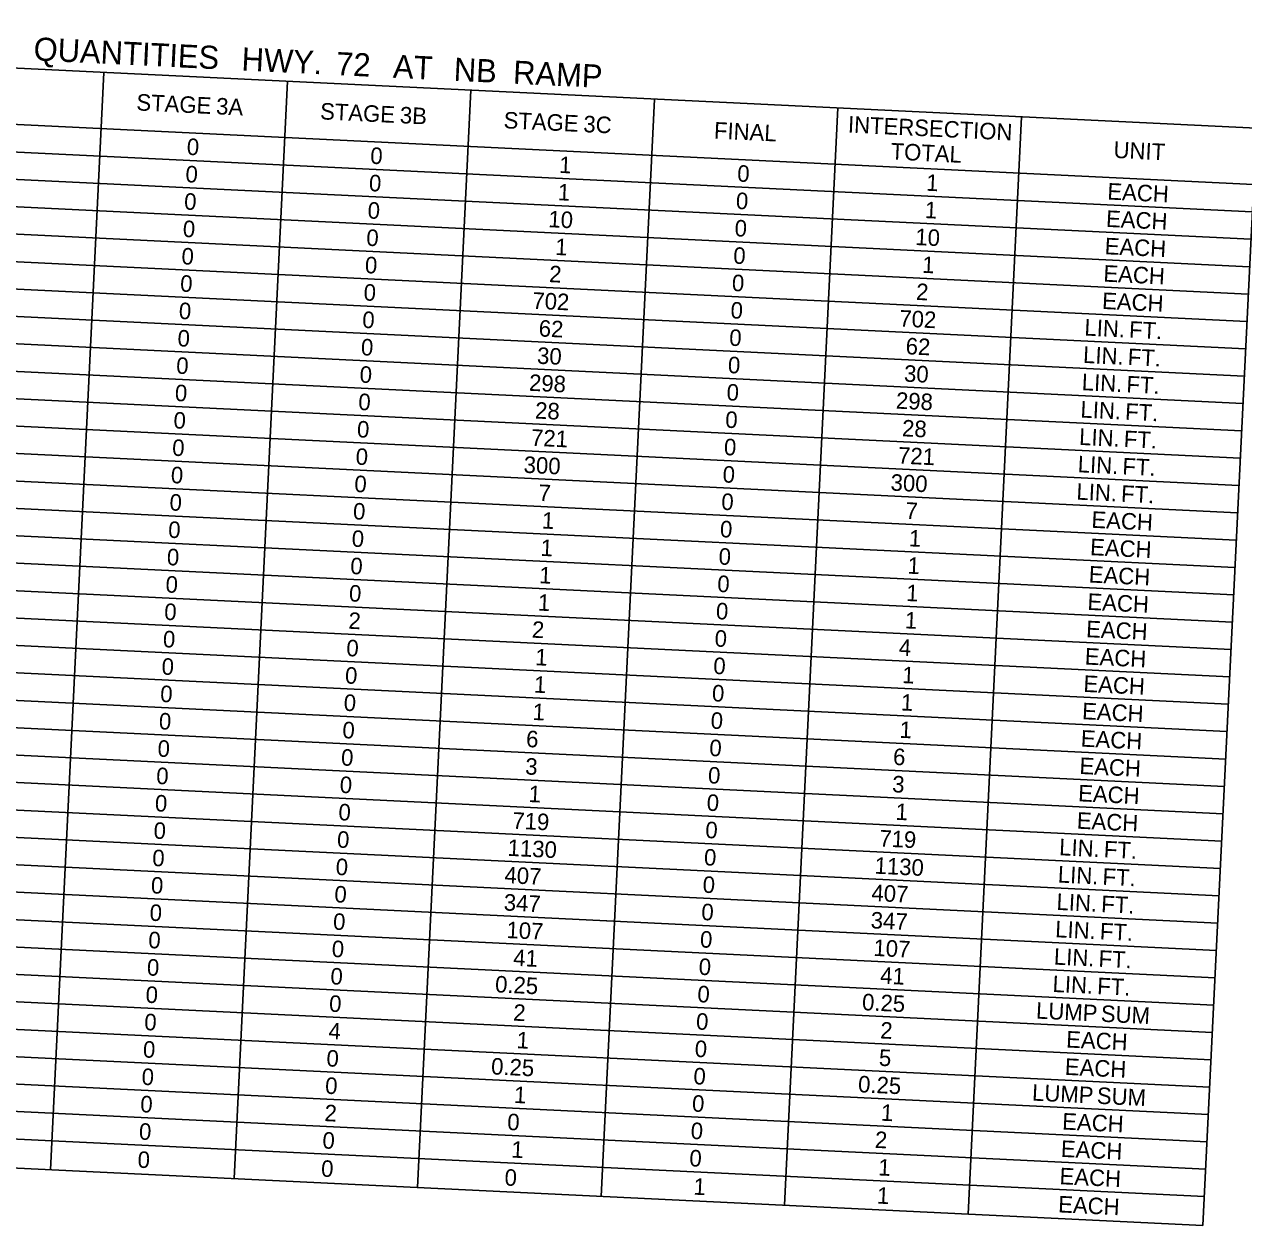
# Model space of a CAD drawing. Extents: x 668933 to 670801, y 741155 to 743955.
# Drawn here: x 669245.8 to 669430.3, y 743471 to 743652.7 of the extents above; entities that cross this region are included whole.
import ezdxf

# ---------------------------------------------------------------- set-up
doc = ezdxf.new("R2010")
doc.units = 0
doc.layers.add('R_Dimension', color=7, linetype='Continuous')

msp = doc.modelspace()

# ---------------------------------------------------------------- linework, layer by layer
at = {"layer": 'R_Dimension'}
for p, q in [((669108.37, 743652.72), (669432.18, 743637)), ((669249.79, 743479.42), (669257.86, 743645.46)), ((669107.96, 743644.2), (669431.76, 743628.48)), ((669277.55, 743478.07), (669285.61, 743644.12)), ((669305.3, 743476.73), (669313.37, 743642.77)), ((669333.06, 743475.38), (669341.12, 743641.42)), ((669107.76, 743640.06), (669431.56, 743624.34)), ((669360.81, 743474.03), (669368.88, 743640.07)), ((669388.57, 743472.68), (669396.63, 743638.72)), ((669107.56, 743635.92), (669431.36, 743620.2)), ((669424.11, 743470.96), (669432.18, 743637)), ((669107.35, 743631.78), (669431.16, 743616.06)), ((669107.15, 743627.65), (669430.96, 743611.92)), ((669106.95, 743623.51), (669430.76, 743607.78)), ((669106.75, 743619.37), (669430.56, 743603.64)), ((669106.55, 743615.23), (669430.36, 743599.51)), ((669106.35, 743611.09), (669430.16, 743595.37)), ((669106.15, 743606.95), (669429.95, 743591.23)), ((669105.95, 743602.81), (669429.75, 743587.09)), ((669105.75, 743598.67), (669429.55, 743582.95)), ((669105.55, 743594.54), (669429.35, 743578.81)), ((669105.34, 743590.4), (669429.15, 743574.67)), ((669105.14, 743586.26), (669428.95, 743570.53)), ((669104.94, 743582.12), (669428.75, 743566.39)), ((669104.74, 743577.98), (669428.55, 743562.26)), ((669104.54, 743573.84), (669428.35, 743558.12)), ((669104.34, 743569.7), (669428.15, 743553.98)), ((669104.14, 743565.56), (669427.94, 743549.84)), ((669103.94, 743561.42), (669427.74, 743545.7)), ((669103.74, 743557.29), (669427.54, 743541.56)), ((669103.54, 743553.15), (669427.34, 743537.42)), ((669103.33, 743549.01), (669427.14, 743533.28)), ((669103.13, 743544.87), (669426.94, 743529.14)), ((669102.93, 743540.73), (669426.74, 743525.01)), ((669102.73, 743536.59), (669426.54, 743520.87)), ((669102.53, 743532.45), (669426.34, 743516.73)), ((669102.33, 743528.31), (669426.14, 743512.59)), ((669102.13, 743524.17), (669425.93, 743508.45)), ((669101.93, 743520.04), (669425.73, 743504.31)), ((669101.73, 743515.9), (669425.53, 743500.17)), ((669101.53, 743511.76), (669425.33, 743496.03)), ((669101.32, 743507.62), (669425.13, 743491.89)), ((669101.12, 743503.48), (669424.93, 743487.76)), ((669100.92, 743499.34), (669424.73, 743483.62)), ((669100.72, 743495.2), (669424.53, 743479.48)), ((669100.52, 743491.06), (669424.33, 743475.34)), ((669100.31, 743486.68), (669424.11, 743470.96))]:
    msp.add_line(p, q, dxfattribs=at)

# ---------------------------------------------------------------- texts
for s, height, p in [(' QUANTITIES', 3.5, (669245.85, 743647.35)), (' HWY.', 3.5, (669277.31, 743645.82)), (' 72', 3.5, (669291.6, 743645.12)), (' AT', 3.5, (669300.22, 743644.71)), (' NB', 3.5, (669309.41, 743644.26)), (' RAMP', 3.5, (669318.38, 743643.82)), ('STAGE', 2.5, (669262.72, 743639.71)), (' 3A', 2.5, (669273.85, 743639.17)), ('STAGE', 2.5, (669290.51, 743638.36)), (' 3B', 2.5, (669301.64, 743637.82)), ('STAGE', 2.5, (669318.27, 743637.01)), (' 3C', 2.5, (669329.4, 743636.47)), ('FINAL', 2.5, (669350.09, 743635.46)), ('INTERSECTION', 2.5, (669370.36, 743636.36)), ('0', 2.5, (669270.34, 743632.99)), ('0', 2.5, (669298.1, 743631.64)), ('TOTAL', 2.5, (669376.81, 743632.29)), ('UNIT', 2.5, (669410.53, 743632.53)), ('1', 2.5, (669326.67, 743630.26)), ('0', 2.5, (669270.14, 743628.85)), ('0', 2.5, (669297.9, 743627.5)), ('0', 2.5, (669353.61, 743628.95)), ('1', 2.5, (669382.18, 743627.56)), ('1', 2.5, (669326.47, 743626.12)), ('EACH', 2.5, (669409.6, 743626.23)), ('0', 2.5, (669269.94, 743624.71)), ('0', 2.5, (669353.41, 743624.81)), ('0', 2.5, (669297.7, 743623.36)), ('10', 2.5, (669325.04, 743622.04)), ('1', 2.5, (669381.98, 743623.42)), ('EACH', 2.5, (669409.4, 743622.09)), ('0', 2.5, (669269.74, 743620.57)), ('0', 2.5, (669353.21, 743620.67)), ('0', 2.5, (669297.5, 743619.23)), ('10', 2.5, (669380.55, 743619.34)), ('0', 2.5, (669269.54, 743616.43)), ('1', 2.5, (669326.07, 743617.84)), ('0', 2.5, (669353.01, 743616.53)), ('EACH', 2.5, (669409.2, 743617.95)), ('0', 2.5, (669297.29, 743615.09)), ('1', 2.5, (669381.58, 743615.14)), ('2', 2.5, (669325.16, 743613.73)), ('EACH', 2.5, (669409, 743613.81)), ('0', 2.5, (669269.34, 743612.3)), ('0', 2.5, (669297.09, 743610.95)), ('0', 2.5, (669352.8, 743612.39)), ('2', 2.5, (669380.67, 743611.04)), ('702', 2.5, (669322.62, 743609.71)), ('EACH', 2.5, (669408.8, 743609.67)), ('0', 2.5, (669269.14, 743608.16)), ('0', 2.5, (669352.6, 743608.25)), ('0', 2.5, (669296.89, 743606.81)), ('62', 2.5, (669323.58, 743605.51)), ('702', 2.5, (669378.13, 743607.01)), ('LIN.', 2.5, (669406.13, 743605.65)), ('0', 2.5, (669268.94, 743604.02)), ('0', 2.5, (669352.4, 743604.11)), (' FT.', 2.5, (669411.95, 743605.37)), ('0', 2.5, (669296.69, 743602.67)), ('62', 2.5, (669379.09, 743602.82)), ('0', 2.5, (669268.74, 743599.88)), ('30', 2.5, (669323.33, 743601.38)), ('0', 2.5, (669352.2, 743599.97)), ('LIN.', 2.5, (669405.93, 743601.51)), (' FT.', 2.5, (669411.75, 743601.23)), ('0', 2.5, (669296.49, 743598.53)), ('30', 2.5, (669378.84, 743598.68)), ('298', 2.5, (669322.11, 743597.29)), ('LIN.', 2.5, (669405.73, 743597.38)), (' FT.', 2.5, (669411.55, 743597.09)), ('0', 2.5, (669268.54, 743595.74)), ('0', 2.5, (669296.29, 743594.39)), ('0', 2.5, (669352, 743595.84)), ('298', 2.5, (669377.62, 743594.59)), ('28', 2.5, (669323.03, 743593.09)), ('LIN.', 2.5, (669405.53, 743593.24)), (' FT.', 2.5, (669411.35, 743592.95)), ('0', 2.5, (669268.33, 743591.6)), ('0', 2.5, (669351.8, 743591.7)), ('0', 2.5, (669296.09, 743590.25)), ('721', 2.5, (669322.42, 743588.98)), ('28', 2.5, (669378.54, 743590.4)), ('LIN.', 2.5, (669405.33, 743589.1)), (' FT.', 2.5, (669411.15, 743588.82)), ('0', 2.5, (669268.13, 743587.46)), ('0', 2.5, (669351.6, 743587.56)), ('0', 2.5, (669295.89, 743586.11)), ('721', 2.5, (669377.93, 743586.28)), ('0', 2.5, (669267.93, 743583.32)), ('300', 2.5, (669321.3, 743584.88)), ('0', 2.5, (669351.4, 743583.42)), ('LIN.', 2.5, (669405.12, 743584.96)), (' FT.', 2.5, (669410.94, 743584.68)), ('0', 2.5, (669295.69, 743581.98)), ('300', 2.5, (669376.81, 743582.19)), ('7', 2.5, (669323.55, 743580.62)), ('LIN.', 2.5, (669404.92, 743580.82)), (' FT.', 2.5, (669410.74, 743580.54)), ('0', 2.5, (669267.73, 743579.18)), ('0', 2.5, (669295.49, 743577.84)), ('0', 2.5, (669351.2, 743579.28)), ('7', 2.5, (669379.06, 743577.93)), ('1', 2.5, (669324.06, 743576.45)), ('EACH', 2.5, (669407.19, 743576.56)), ('0', 2.5, (669267.53, 743575.05)), ('0', 2.5, (669351, 743575.14)), ('0', 2.5, (669295.29, 743573.7)), ('1', 2.5, (669323.86, 743572.31)), ('1', 2.5, (669379.57, 743573.75)), ('EACH', 2.5, (669406.99, 743572.42)), ('0', 2.5, (669267.33, 743570.91)), ('0', 2.5, (669350.79, 743571)), ('0', 2.5, (669295.08, 743569.56)), ('1', 2.5, (669379.37, 743569.62)), ('0', 2.5, (669267.13, 743566.77)), ('1', 2.5, (669323.65, 743568.17)), ('0', 2.5, (669350.59, 743566.86)), ('EACH', 2.5, (669406.79, 743568.28)), ('0', 2.5, (669294.88, 743565.42)), ('1', 2.5, (669379.16, 743565.48)), ('1', 2.5, (669323.45, 743564.03)), ('EACH', 2.5, (669406.59, 743564.14)), ('0', 2.5, (669266.93, 743562.63)), ('2', 2.5, (669294.79, 743561.28)), ('0', 2.5, (669350.39, 743562.73)), ('1', 2.5, (669378.96, 743561.34)), ('2', 2.5, (669322.55, 743559.93)), ('EACH', 2.5, (669406.39, 743560.01)), ('0', 2.5, (669266.73, 743558.49)), ('0', 2.5, (669350.19, 743558.59)), ('0', 2.5, (669294.48, 743557.14)), ('1', 2.5, (669323.05, 743555.76)), ('4', 2.5, (669378.05, 743557.23)), ('EACH', 2.5, (669406.19, 743555.87)), ('0', 2.5, (669266.53, 743554.35)), ('0', 2.5, (669349.99, 743554.45)), ('0', 2.5, (669294.28, 743553)), ('1', 2.5, (669378.56, 743553.06)), ('0', 2.5, (669266.32, 743550.21)), ('1', 2.5, (669322.85, 743551.62)), ('0', 2.5, (669349.79, 743550.31)), ('EACH', 2.5, (669405.98, 743551.73)), ('0', 2.5, (669294.08, 743548.87)), ('1', 2.5, (669378.36, 743548.92)), ('1', 2.5, (669322.65, 743547.48)), ('EACH', 2.5, (669405.78, 743547.59)), ('0', 2.5, (669266.12, 743546.07)), ('0', 2.5, (669293.88, 743544.73)), ('0', 2.5, (669349.59, 743546.17)), ('1', 2.5, (669378.16, 743544.78)), ('6', 2.5, (669321.67, 743543.38)), ('EACH', 2.5, (669405.58, 743543.45)), ('0', 2.5, (669265.92, 743541.94)), ('0', 2.5, (669349.39, 743542.03)), ('0', 2.5, (669293.68, 743540.59)), ('3', 2.5, (669321.54, 743539.23)), ('6', 2.5, (669377.18, 743540.68)), ('EACH', 2.5, (669405.38, 743539.31)), ('0', 2.5, (669265.72, 743537.8)), ('0', 2.5, (669349.19, 743537.89)), ('0', 2.5, (669293.48, 743536.45)), ('3', 2.5, (669377.05, 743536.54)), ('0', 2.5, (669265.52, 743533.66)), ('1', 2.5, (669322.05, 743535.06)), ('0', 2.5, (669348.99, 743533.75)), ('EACH', 2.5, (669405.18, 743535.17)), ('0', 2.5, (669293.28, 743532.31)), ('1', 2.5, (669377.56, 743532.37)), ('719', 2.5, (669319.59, 743531.03)), ('EACH', 2.5, (669404.98, 743531.03)), ('0', 2.5, (669265.32, 743529.52)), ('0', 2.5, (669293.07, 743528.17)), ('0', 2.5, (669348.78, 743529.61)), ('719', 2.5, (669375.1, 743528.34)), ('1130', 2.5, (669318.88, 743526.92)), ('LIN.', 2.5, (669402.31, 743527.01)), (' FT.', 2.5, (669408.13, 743526.73)), ('0', 2.5, (669265.12, 743525.38)), ('0', 2.5, (669348.58, 743525.48)), ('0', 2.5, (669292.87, 743524.03)), ('407', 2.5, (669318.4, 743522.79)), ('1130', 2.5, (669374.39, 743524.22)), ('LIN.', 2.5, (669402.11, 743522.88)), (' FT.', 2.5, (669407.93, 743522.59)), ('0', 2.5, (669264.92, 743521.24)), ('0', 2.5, (669348.38, 743521.34)), ('0', 2.5, (669292.67, 743519.89)), ('347', 2.5, (669318.29, 743518.65)), ('407', 2.5, (669373.91, 743520.1)), ('LIN.', 2.5, (669401.91, 743518.74)), ('0', 2.5, (669264.72, 743517.1)), ('0', 2.5, (669348.18, 743517.2)), (' FT.', 2.5, (669407.73, 743518.45)), ('0', 2.5, (669292.47, 743515.75)), ('347', 2.5, (669373.8, 743515.95)), ('107', 2.5, (669318.7, 743514.48)), ('LIN.', 2.5, (669401.71, 743514.6)), (' FT.', 2.5, (669407.53, 743514.32)), ('0', 2.5, (669264.52, 743512.96)), ('0', 2.5, (669292.27, 743511.62)), ('0', 2.5, (669347.98, 743513.06)), ('107', 2.5, (669374.21, 743511.78)), ('41', 2.5, (669319.72, 743510.28)), ('LIN.', 2.5, (669401.51, 743510.46)), (' FT.', 2.5, (669407.33, 743510.18)), ('0', 2.5, (669264.31, 743508.82)), ('0', 2.5, (669347.78, 743508.92)), ('0', 2.5, (669292.07, 743507.48)), ('0.25', 2.5, (669316.98, 743506.27)), ('41', 2.5, (669375.23, 743507.59)), ('LIN.', 2.5, (669401.31, 743506.32)), (' FT.', 2.5, (669407.13, 743506.04)), ('0', 2.5, (669264.11, 743504.69)), ('0', 2.5, (669347.58, 743504.78)), ('0', 2.5, (669291.87, 743503.34)), ('0.25', 2.5, (669372.49, 743503.57)), ('LUMP', 2.5, (669398.81, 743502.29)), ('0', 2.5, (669263.91, 743500.55)), ('2', 2.5, (669319.73, 743501.98)), ('0', 2.5, (669347.38, 743500.64)), (' SUM', 2.5, (669407.68, 743501.86)), ('4', 2.5, (669291.78, 743499.19)), ('2', 2.5, (669375.24, 743499.29)), ('1', 2.5, (669320.24, 743497.81)), ('EACH', 2.5, (669403.37, 743497.92)), ('0', 2.5, (669263.71, 743496.41)), ('0', 2.5, (669291.47, 743495.06)), ('0', 2.5, (669347.18, 743496.5)), ('5', 2.5, (669375.04, 743495.15)), ('0.25', 2.5, (669316.38, 743493.85)), ('EACH', 2.5, (669403.17, 743493.78)), ('0', 2.5, (669263.51, 743492.27)), ('0', 2.5, (669346.98, 743492.36)), ('0.25', 2.5, (669371.89, 743491.15)), ('0', 2.5, (669291.27, 743490.92)), ('1', 2.5, (669319.84, 743489.53)), ('LUMP', 2.5, (669398.21, 743489.88)), (' SUM', 2.5, (669407.08, 743489.45)), ('0', 2.5, (669263.31, 743488.13)), ('0', 2.5, (669346.77, 743488.23)), ('2', 2.5, (669291.17, 743486.78)), ('1', 2.5, (669375.35, 743486.84)), ('EACH', 2.5, (669402.77, 743485.51)), ('0', 2.5, (669263.11, 743483.99)), ('0', 2.5, (669318.82, 743485.43)), ('0', 2.5, (669346.57, 743484.09)), ('0', 2.5, (669290.86, 743482.64)), ('2', 2.5, (669374.44, 743482.73)), ('1', 2.5, (669319.43, 743481.26)), ('0', 2.5, (669346.37, 743479.95)), ('EACH', 2.5, (669402.57, 743481.37)), ('0', 2.5, (669262.9, 743479.73)), ('0', 2.5, (669290.66, 743478.38)), ('1', 2.5, (669374.94, 743478.56)), ('0', 2.5, (669318.41, 743477.03)), ('EACH', 2.5, (669402.37, 743477.23)), ('1', 2.5, (669346.98, 743475.65)), ('1', 2.5, (669374.74, 743474.3)), ('EACH', 2.5, (669402.16, 743472.97))]:
    msp.add_text(s, height=height, rotation=357.2199, dxfattribs=at).set_placement(p)

doc.saveas('drawing.dxf')
